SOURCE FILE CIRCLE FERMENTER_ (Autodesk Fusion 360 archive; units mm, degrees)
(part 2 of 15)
sketch "Schizzo17" plane through (0, 0, -13.5) normal (0, 0, 1) x axis (-1, 0, 0)
  line L1 (-125, 90) -> (-125, 88.4)
  line L2 (-160, 90) -> (-125, 90)
  line L3 (-160, 88.4) -> (-160, 90)
  curve K1 (-142.5, 81.4) -> (-160, 88.4)
  curve K2 (-135, 85.4) -> (-142.5, 81.4)
  line L4 (-135, 88.4) -> (-135, 85.4)
  line L5 (-125, 88.4) -> (-135, 88.4)
  line L6 (-136.6, 88.4) -> (-136.6, 86.8515)
  line L7 (-152.9954, 88.4) -> (-136.6, 88.4)
  curve K3 (-142.5, 83) -> (-152.9954, 88.4)
  curve K4 (-136.6, 86.8515) -> (-142.5, 83)
  line L8 (-138.6, 88.4) -> (-138.6, 86.0053)
  point P13 (-138.6, 86.0053)
  point P14 (-138.6, 88.4)
  coincident K4 P13
  coincident L7 P14
  perpendicular L7 L8
  dimension "d275" = -1.6
  dimension "d672" distance L6 L8 = 2
extrude "Estrusione20" cut sketch "Schizzo17" profile of K3 K4 L7 L8 against normal blind 50
sweep "Sweep3" TwistAngle 0 TaperAngle 0
fillet "Raccordo1" radius 0.5
extrude "Estrusione21" cut of existing geometry blind -45 (= "-120 mm + 75 mm")
sketch "Schizzo18" plane through (0, -15, 0) normal (0, 1, 0) x axis (-1, 0, 0)
  line L1 (-150.8209, -86.9) -> (-138.6, -86.9)
  curve K1 (-150.8209, -86.9) -> (-151.0572, -85.9594)
  curve K2 (-142.5, -81.5) -> (-151.0572, -85.9594)
  curve K3 (-138.6, -84.5053) -> (-142.5, -81.5)
  line L2 (-125, -86.9) -> (-125, -88.5)
  line L3 (-135, -86.9) -> (-125, -86.9)
  line L4 (-135, -83.9) -> (-135, -86.9)
  curve K4 (-135, -83.9) -> (-142.5, -79.9)
  curve K5 (-142.5, -79.9) -> (-160, -86.9)
  line L5 (-160, -88.5) -> (-160, -86.9)
  line L6 (-125, -88.5) -> (-160, -88.5)
  line L7 (-138.6, -86.9) -> (-138.6, -84.5053)
  circle C1 centre (-135.4, -85.4) radius 0.85
  point P14 (-135.4, -85.4)
  dimension "DIAM_SEDE_GUARNIZOIONE" diameter C1 = 1.7
  dimension "d669" distance L4 P14 = 0.4
  dimension "d671" distance L3 P14 = 1.5
sweep "Sweep4" sketch "Schizzo18" TwistAngle 0 TaperAngle 0
mirror "Specchio2" mirrorStitchTolerance 0.1
sketch "Schizzo19" plane through (0, -15, 0) normal (0, 1, 0) x axis (-1, 0, 0)
  line L1 (-135, -83.9) -> (-135, -84.65)
  curve K1 (-135, -83.9) -> (-142.5, -79.9)
  curve K2 (-142.5, -79.9) -> (-160, -86.9)
  line L2 (-160, -88.5) -> (-160, -86.9)
  line L3 (-125, -88.5) -> (-160, -88.5)
  line L4 (-125, -86.9) -> (-125, -88.5)
  line L5 (-135, -86.9) -> (-125, -86.9)
  line L6 (-150.8209, -86.9) -> (-138.6, -86.9)
  curve K3 (-150.8209, -86.9) -> (-151.0572, -85.9594)
  curve K4 (-142.5, -81.5) -> (-151.0572, -85.9594)
  curve K5 (-138.6, -84.5053) -> (-142.5, -81.5)
  line L7 (-135, -86.15) -> (-135, -86.9)
  line L8 (-138.6, -86.9) -> (-138.6, -84.5053)
  arc A1 centre (-135.4, -85.4) radius 0.85 clockwise from (-135, -86.15) to (-135, -84.65)
  arc A2 centre (-135.4, -85.4) radius 0.85 clockwise from (-135, -86.15) to (-135, -84.65)
  circle C1 centre (-135.4, -85.4) radius 0.875
  concentric A2 C1
  dimension "d305" diameter C1 = 1.75
sweep "Sweep5" sketch "Schizzo19" TwistAngle 0 TaperAngle 0 bodies "GUARNIZIONE"
mirror "Specchio3" mirrorStitchTolerance 0.1 bodies "GUARNIZIONE (1)"
work_plane "Piano di lavoro2" AlongDistance -2
sketch "Schizzo21" plane through (158, 0, 0) normal (1, 0, 0) x axis (0, 1, 0)
  line L1 (-81.4, -63.5) -> (-81.4, -13.5)
  curve K1 (-81.4, -63.5) -> (-65, -79.9)
  line L2 (-65, -79.9) -> (-15, -79.9)
  line L3 (-65, -81.4) -> (-15, -81.4)
  curve K2 (-82.9, -63.5) -> (-65, -81.4)
  line L4 (-82.9, -63.5) -> (-82.9, -13.5)
  line L5 (-15, -13.5) -> (-15, -81.4)
  line L6 (-82.9, -13.5) -> (-15, -13.5)
  horizontal L6
  vertical L5
  dimension "d329" = -1.5
extrude "Estrusione23" new body sketch "Schizzo21" profile of L3 K2 L4 L5 L6 against normal blind 3 bodies "TEST ACRILICO DAVANTI"
sketch "Schizzo22" plane through (0, 0, -13.5) normal (0, 0, 1) x axis (-1, 0, 0)
  line L1 (-125, 88.4) -> (-135, 88.4)
  line L2 (-125, 90) -> (-125, 88.4)
  line L3 (-160, 90) -> (-125, 90)
  line L4 (-160, 88.4) -> (-160, 90)
  curve K1 (-142.5, 81.4) -> (-160, 88.4)
  curve K2 (-135, 85.4) -> (-142.5, 81.4)
  line L5 (-135, 88.4) -> (-135, 87.65)
  curve K3 (-142.5, 83) -> (-138.6, 86.0053)
  curve K4 (-151.0572, 87.4594) -> (-142.5, 83)
  curve K5 (-151.0572, 87.4594) -> (-150.8209, 88.4)
  line L6 (-138.6, 88.4) -> (-150.8209, 88.4)
  curve K6 (-142.5, 80.9) -> (-160, 87.9)
  line L7 (-160, 90) -> (-160, 87.9)
  line L8 (-158, 15) -> (-158, 82.9)
  line L9 (-155, 15) -> (-158, 15)
  line L10 (-155, 82.9) -> (-155, 15)
  line L11 (-158, 82.9) -> (-155, 82.9)
  line L12 (-158, 82.9) -> (-158, 77.9)
  line L13 (-155, 82.9) -> (-158, 82.9)
  line L14 (-155, 86.9365) -> (-155, 82.9)
  curve K7 (-164, 77.9) -> (-158, 77.9)
  curve K8 (-168, 77.9) -> (-164, 77.9)
  curve K9 (-170, 88.4) -> (-168, 77.9)
  curve K10 (-174, 88.4) -> (-170, 88.4)
  curve K11 (-180, 88.4) -> (-174, 88.4)
  curve K12 (-180, 88.4) -> (-158, 77.9)
  line L15 (-160, 90) -> (-160, 87.9)
  line L16 (-180, 90) -> (-160, 90)
  line L17 (-180, 88.4) -> (-180, 90)
  line L18 (-151.4, 82.9) -> (-155, 82.9)
  line L19 (-151.4, 85.247) -> (-151.4, 82.9)
  line L20 (-138.6, 86.0053) -> (-138.6, 88.4)
  line L21 (-135, 86.15) -> (-135, 85.4)
  arc A1 centre (-135.4, 86.9) radius 0.85 clockwise from (-135, 86.15) to (-135, 87.65)
  point P7 (-160, 90)
  point P18 (-160, 90)
  point P23 (-158, 77.9)
  point P19 (-158, 82.9)
  point P24 (-158, 82.9)
  point P22 (-155, 82.9)
  point P25 (-155, 82.9)
  point P26 (-155, 82.9)
  point P27 (-155, 86.9365)
  point P33 (-160, 90)
  point P36 (-151.4, 85.247)
  point P28 (-164, 77.9)
  point P29 (-168, 77.9)
  point P31 (-174, 88.4)
  point P32 (-180, 88.4)
  point P30 (-170, 88.4)
  point P34 (-180, 90)
  point P35 (-151.4, 82.9)
  coincident P7 P18
  perpendicular L3 L7
  coincident L8 P23
  coincident P19 P24
  perpendicular L11 L12
  coincident P22 P25
  coincident P22 P26
  coincident K6 P27
  perpendicular L11 L14
  horizontal K10
  horizontal K7
  perpendicular L15 L16
  parallel L15 L17
  horizontal K8
  horizontal K11
  coincident P18 P33
  perpendicular L14 L18
  coincident K6 P36
  perpendicular L18 L19
  dimension "d332" = 0.5
  dimension "d335" distance P23 P24 = 5
  dimension "d336" distance L3 L13 = 7.1
  dimension "d337" distance P23 P28 = 6
  dimension "d338" distance P23 P29 = 10
  dimension "d339" distance P31 P32 = 6
  dimension "d340" distance P30 P32 = 10
  dimension "d342" distance P32 P34 = 1.6
  dimension "d343" distance P33 P34 = 20
  dimension "d373" distance P25 P35 = 3.6
extrude "Estrusione24" new body sketch "Schizzo22" profile of L4 K6 L7 L8 L11 L12 L13 L14 K12 L15 L16 L17 against normal blind 50
sweep "Sweep6" TwistAngle 0 TaperAngle 0 bodies "PROFILO BASE PORTA"
remove_body "RimuoviCorpo1"
chamfer "Smusso2" distance 0.8
component_from_bodies "Corpo->Comp1"
component_from_bodies "Corpo->Comp2"
copy_paste "CopiaIncolla1"
extrude "Estrusione1" add of existing geometry blind 27.5 (= "( 205 / 2 ) * 1 mm - 75 mm")
extrude "Estrusione2" add of existing geometry blind 15 (= "90 mm - 75 mm")
remove_instance "RimuoviIstanza1"
extrude "Estrusione3" add of existing geometry blind 85 (= "( 320 / 2 ) * 1 mm - 75 mm")
mirror_component "SpecchiaComponente1"
derived_instance "DerivedInstance1"
mirror_component "SpecchiaComponente2"
derived_instance "DerivedInstance2"
derived_instance "DerivedInstance3"
copy_paste "CopiaIncolla2"
extrude "Estrusione1" add of existing geometry blind 15
extrude "Estrusione2" add of existing geometry blind 27.5
sketch "Schizzo3" plane through (0, 0, 0) normal (0, 1, 0) x axis (-1, 0, 0)
  line L1 (-160, -87.7) -> (-160.8, -88.5)
  line L2 (-160, -86.4) -> (-160, -87.7)
  curve K1 (-151.4, -83.747) -> (-160, -86.4)
  line L3 (-151.4, -81.4) -> (-151.4, -83.747)
  line L4 (-158, -81.4) -> (-151.4, -81.4)
  line L5 (-158, -76.4) -> (-158, -81.4)
  curve K2 (-180, -86.9) -> (-158, -76.4)
  line L6 (-180, -88.5) -> (-180, -86.9)
  line L7 (-160.8, -88.5) -> (-180, -88.5)
  line L8 (-158, -86.2311) -> (-158, -81.4)
  point P7 (-158, -81.4)
  point P11 (-158, -81.4)
  point P12 (-158, -86.2311)
  coincident P7 P11
  coincident K1 P12
  perpendicular L4 L8
extrude "Estrusione5" cut sketch "Schizzo3" profile of K1 L3 L4 L8 against normal blind 65
sketch "Schizzo4" plane through (0, 0, 14) normal (0, 0, 1) x axis (-1, 0, 0)
  line L1 (-160.8, 90) -> (-160, 89.2)
  line L2 (-180, 90) -> (-160.8, 90)
  line L3 (-180, 88.4) -> (-180, 90)
  curve K1 (-158, 77.9) -> (-180, 88.4)
  line L4 (-158, 82.9) -> (-158, 77.9)
  line L5 (-151.4, 82.9) -> (-158, 82.9)
  line L6 (-151.4, 85.247) -> (-151.4, 82.9)
  curve K2 (-160, 87.9) -> (-151.4, 85.247)
  line L7 (-160, 89.2) -> (-160, 87.9)
  line L8 (-158, 87.7311) -> (-158, 82.9)
  point P7 (-158, 82.9)
  point P11 (-158, 82.9)
  point P12 (-158, 87.7311)
  coincident P7 P11
  coincident K2 P12
  perpendicular L5 L8
extrude "Estrusione6" cut sketch "Schizzo4" profile of L5 L6 K2 L8 against normal blind 77.5 alignOffsetY 0
sketch "Schizzo6" plane through (158, 0, 0) normal (-1, 0, 0) x axis (0, -1, 0)
  curve K1 (65, -76.4) -> (77.9, -63.5)
  line L1 (0, -76.4) -> (65, -76.4)
  line L2 (0, -86.2311) -> (0, -76.4)
  line L3 (0, -86.2311) -> (65, -86.2311)
  line L4 (65, -81.4) -> (65, -86.2311)
  curve K2 (65, -81.4) -> (82.9, -63.5)
  line L5 (87.7311, -63.5) -> (82.9, -63.5)
  line L6 (87.7311, -63.5) -> (87.7311, 14)
  line L7 (77.9, 14) -> (87.7311, 14)
  line L8 (77.9, -63.5) -> (77.9, 14)
  line L9 (86.9, -62.4362) -> (86.9, -63.5)
  line L10 (86.9, 14) -> (86.9, -62.4362)
  line L11 (0, -85.4) -> (65, -85.4)
  line L12 (0, 14) -> (0, -85.4)
  line L13 (86.9, 14) -> (0, 14)
  point P12 (86.9, -63.5)
  point P14 (86.9, 14)
  point P15 (65, -85.4)
  point P16 (0, -85.4)
  coincident L5 P12
  perpendicular L5 L9
  coincident L7 P14
  perpendicular L7 L10
  coincident L4 P15
  coincident L2 P16
  perpendicular L2 L11
  horizontal L13
  vertical L12
  dimension "d398" distance L10 L12 = 86.9
  dimension "d399" distance L11 L13 = 99.4
extrude "Estrusione7" new body sketch "Schizzo6" profile of K1 L1 L2 L4 K2 L5 L7 L8 L9 L10 L11 L12 L13 along normal blind 3 bodies "ACRILICO SPORTELLO"
sketch "Schizzo7" plane through (0, 0, 14) normal (0, 0, 1) x axis (-1, 0, 0)
  line L1 (-158, 87.7311) -> (-158, 77.9)
  curve K1 (-160, 87.9) -> (-158, 87.7311)
  line L2 (-160, 89.2) -> (-160, 87.9)
  line L3 (-160.8, 90) -> (-160, 89.2)
  line L4 (-180, 90) -> (-160.8, 90)
  line L5 (-180, 88.4) -> (-180, 90)
  curve K2 (-158, 77.9) -> (-180, 88.4)
  line L6 (-151.4, 85.247) -> (-151.4, 82.9)
  curve K3 (-151.4, 85.247) -> (-158, 87.7311)
  line L7 (-158, 82.9) -> (-158, 87.7311)
  line L8 (-151.4, 82.9) -> (-158, 82.9)
  line L9 (-158, 0) -> (-158, 86.9)
  line L10 (-155, 0) -> (-158, 0)
  line L11 (-155, 86.9) -> (-155, 0)
  line L12 (-158, 86.9) -> (-155, 86.9)
  line L13 (-155, 88.0285) -> (-155, 86.9)
  point P16 (-155, 86.9)
  point P17 (-155, 86.9)
  coincident P16 P17
  perpendicular L12 L13
extrude "Estrusione8" new body sketch "Schizzo7" profile of L6 K3 L8 L11 L13 against normal blind 77.5
sketch "Schizzo8" plane through (0, 0, 0) normal (0, 1, 0) x axis (-1, 0, 0)
  line L1 (-158, -76.4) -> (-158, -86.2311)
  curve K1 (-180, -86.9) -> (-158, -76.4)
  line L2 (-180, -88.5) -> (-180, -86.9)
  line L3 (-160.8, -88.5) -> (-180, -88.5)
  line L4 (-160, -87.7) -> (-160.8, -88.5)
  line L5 (-160, -86.4) -> (-160, -87.7)
  curve K2 (-158, -86.2311) -> (-160, -86.4)
  line L6 (-158, -85.4) -> (-158, 14)
  line L7 (-155, -85.4) -> (-158, -85.4)
  line L8 (-155, 14) -> (-155, -85.4)
  line L9 (-158, 14) -> (-155, 14)
  line L10 (-158, -86.2311) -> (-158, -81.4)
  curve K3 (-151.4, -83.747) -> (-158, -86.2311)
  line L11 (-151.4, -81.4) -> (-151.4, -83.747)
  line L12 (-158, -81.4) -> (-151.4, -81.4)
  line L13 (-155, -87.0144) -> (-155, -85.4)
  point P11 (-155, -85.4)
  point P17 (-155, -85.4)
  coincident P11 P17
  perpendicular L7 L13
extrude "Estrusione9" new body sketch "Schizzo8" profile of L8 K3 L11 L12 L13 against normal blind 65
sketch "Schizzo9" plane through (155, 0, 0) normal (-1, 0, 0) x axis (0, -1, 0)
  line L1 (65, -81.4) -> (65, -85.4)
  curve K1 (82.9, -63.5) -> (65, -81.4)
  line L2 (86.9, -63.5) -> (82.9, -63.5)
  line L3 (86.9, 14) -> (86.9, -63.5)
  line L4 (0, 14) -> (86.9, 14)
  line L5 (0, -85.4) -> (0, 14)
  line L6 (65, -85.4) -> (0, -85.4)
  curve K2 (65, -76.4) -> (77.9, -63.5)
  line L7 (77.9, 14) -> (77.9, -63.5)
  line L8 (0, -76.4) -> (65, -76.4)
  line L9 (65, -81.4) -> (0, -81.4)
  line L10 (82.9, 14) -> (85.247, 14)
  line L11 (82.9, -63.5) -> (82.9, 14)
  line L12 (85.247, -63.5) -> (82.9, -63.5)
  line L13 (85.247, 14) -> (85.247, -63.5)
extrude "Estrusione10" add sketch "Schizzo9" profile of K1 L4 L5 K2 L7 L8 L9 L11 along normal blind 3.6
sketch "Schizzo10" plane through (151.4, 0, 0) normal (-1, 0, 0) x axis (0, -1, 0)
  line L1 (77.9, 14) -> (85.247, 14)
  line L2 (77.9, -63.5) -> (77.9, 14)
  curve K1 (65, -76.4) -> (77.9, -63.5)
  line L3 (0, -76.4) -> (65, -76.4)
  line L4 (0, -83.747) -> (0, -76.4)
  line L5 (65, -83.747) -> (0, -83.747)
  line L6 (65, -81.4) -> (65, -83.747)
  curve K2 (82.9, -63.5) -> (65, -81.4)
  line L7 (85.247, -63.5) -> (82.9, -63.5)
  line L8 (85.247, 14) -> (85.247, -63.5)
  line L9 (65, -63.5) -> (65, -81.4)
  line L10 (82.9, -63.5) -> (65, -63.5)
  line L11 (91.705, -90.205) -> (65, -63.5)
  line L12 (65, -80.0735) -> (0, -80.0735)
  line L13 (81.5735, -63.5) -> (81.5735, 14)
  point P9 (65, -81.4)
  point P12 (65, -81.4)
  point P10 (82.9, -63.5)
  point P14 (82.9, -63.5)
  point P16 (0, -80.0735)
  point P17 (65, -80.0735)
  point P18 (0, -80.0735)
  point P19 (45, -80.0735)
  point P20 (81.5735, 14)
  point P21 (81.5735, -63.5)
  point P22 (81.5735, -43.5)
  point P23 (81.5735, 14)
  coincident P9 P12
  parallel L6 L9
  coincident P10 P14
  horizontal L10
  midpoint L4 P16
  coincident L9 P17
  perpendicular L9 L12
  coincident L12 P18
  coincident L12 P19
  midpoint L1 P20
  coincident L10 P21
  perpendicular L10 L13
  coincident L13 P22
  coincident L13 P23
  coincident P16 P18
  coincident P20 P23
  dimension "d406" angle L10 L11 = 45
  dimension "d408" distance P18 P19 = 45
  dimension "d409" distance L6 P19 = 20
  dimension "d410" distance P21 P22 = 20
  dimension "d413" distance P20 P22 = 57.5
  dimension "d648" distance P22 P23 = 57.5
hole "Foratura1" HoleDepth 12 HoleDiameter 3.5 TipAngle 180 CBDepth 3 CBDiameter 6
fillet "Raccordo2" radius 0.5
mirror "Specchio3" mirrorStitchTolerance 0.1
mirror "Specchio4" mirrorStitchTolerance 0.1
step "Vite5"
joint "Assembla5" alignAngle 0 alignOffsetX 0 alignOffsetY 0 alignOffsetZ 0
step "Vite6"
joint "Assembla6" alignAngle 0 alignOffsetX 0 alignOffsetY 0 alignOffsetZ 0
step "Vite7"
joint "Assembla7" alignAngle 0 alignOffsetX 0 alignOffsetY 0 alignOffsetZ 0
step "Vite8"
joint "Assembla8" alignAngle 0 alignOffsetX 0 alignOffsetY 0 alignOffsetZ 0
step "Vite9"
joint "Assembla9" alignAngle 0 alignOffsetX 0 alignOffsetY 0 alignOffsetZ 0
step "Vite10"
joint "Assembla10" alignAngle 0 alignOffsetX 0 alignOffsetY 0 alignOffsetZ 0
step "Vite11"
joint "Assembla11" alignAngle 0 alignOffsetX 0 alignOffsetY 0 alignOffsetZ 0
step "Vite12"
joint "Assembla12" alignAngle 0 alignOffsetX 0 alignOffsetY 0 alignOffsetZ 0
step "Vite13"
joint "Assembla13" alignAngle 0 alignOffsetX 0 alignOffsetY 0 alignOffsetZ 0
step "Vite14"
joint "Assembla14" alignAngle 0 alignOffsetX 0 alignOffsetY 0 alignOffsetZ 0
step "Vite15"
joint "Assembla15" alignAngle 0 alignOffsetX 0 alignOffsetY 0 alignOffsetZ 0
step "Vite16"
joint "Assembla16" alignAngle 0 alignOffsetX 0 alignOffsetY 0 alignOffsetZ 0
step "Vite17"
joint "Assembla17" alignAngle 0 alignOffsetX 0 alignOffsetZ 0
step "Vite18"
joint "Assembla18" alignAngle 0 alignOffsetX 0 alignOffsetY 0 alignOffsetZ 0
step "Vite19"
joint "Assembla19" alignAngle 0 alignOffsetX 0 alignOffsetY 0 alignOffsetZ 0
step "Vite20"
joint "Assembla20" alignAngle 0 alignOffsetX 0 alignOffsetY 0 alignOffsetZ 0
component_from_bodies "Corpo->Comp1"
mirror "Specchio5" mirrorStitchTolerance 0.1
mirror "Specchio6" mirrorStitchTolerance 0.1
component_from_bodies "Corpo->Comp2"
thread "Filettatura1"
mirror "Specchio1" mirrorStitchTolerance 0.1
mirror "Specchio2" mirrorStitchTolerance 0.1
component_from_bodies "Corpo->Comp3"
joint "Assembla21" alignAngle 0 alignOffsetX 0 alignOffsetY 0 alignOffsetZ 0
joint "Assembla22" alignAngle 0 alignOffsetX 0 alignOffsetY 0 alignOffsetZ 0
chamfer "Smusso1" distance 1
sketch "Schizzo1" plane through (0, 0, 0) normal (-1, 0, 0) x axis (0, -1, 0)
  curve K1 (66.6, -86.8951) -> (88.3975, -65.1)
  line L1 (66.6, -85.4521) -> (66.6, -86.8951)
  curve K2 (79.5815, -78.0815) -> (66.6, -85.4521)
  curve K3 (86.9521, -65.1) -> (79.5815, -78.0815)
  line L2 (88.3975, -65.1) -> (86.9521, -65.1)
  line L3 (85.4, -63.5) -> (86.15, -63.5)
  curve K4 (78.4501, -76.9501) -> (85.4, -63.5)
  curve K5 (65, -83.9) -> (78.4501, -76.9501)
  line L4 (65, -84.65) -> (65, -83.9)
  line L5 (55, -86.9) -> (65, -86.9)
  line L6 (55, -88.5) -> (55, -86.9)
  line L7 (65, -88.5) -> (55, -88.5)
  curve K6 (90, -63.5) -> (65, -88.5)
  line L8 (90, -53.5) -> (90, -63.5)
  line L9 (88.4, -53.5) -> (90, -53.5)
  line L10 (88.4, -63.5) -> (88.4, -53.5)
  line L11 (65, -86.9) -> (65, -86.15)
  line L12 (87.65, -63.5) -> (88.4, -63.5)
  arc A1 centre (86.9, -63.9) radius 0.85 clockwise from (87.65, -63.5) to (86.15, -63.5)
  arc A2 centre (65.4, -85.4) radius 0.85 clockwise from (65, -84.65) to (65, -86.15)
extrude "Estrusione1" new body sketch "Schizzo1" profile of K1 L1 K2 K3 L2 against normal blind 30
fillet "Raccordo1" radius 1
work_plane "Piano di lavoro1"
remove_instance "RimuoviIstanza1"
remove_body "RimuoviCorpo4"
component_from_bodies "Corpo->Comp3"
component_from_bodies "Corpo->Comp4"
extrude "Estrusione1" add of existing geometry blind 85
extrude "Estrusione2" add of existing geometry blind 27.5
extrude "Estrusione1" add of existing geometry blind 85
extrude "Estrusione2" add of existing geometry blind 15
remove_body "RimuoviCorpo7"
remove_body "RimuoviCorpo8"
sketch "Schizzo2" plane through (0, -79.2125, -79.2737) normal (0, -0.7068, -0.7074) x axis (1, 0, 0)
  line L1 (0, 11.5655) -> (30, 11.5655)
  line L2 (30, 11.5655) -> (30, 1.1037)
  line L3 (0, 1.1037) -> (30, 1.1037)
  line L4 (0, 11.5655) -> (0, 1.1037)
  line L5 (30, -9.3661) -> (0, -9.3661)
  line L6 (0, 1.1037) -> (0, -9.3661)
  line L7 (30, 1.1037) -> (0, 1.1037)
  line L8 (30, 1.1037) -> (30, -9.3661)
  circle C1 centre (15, 1.1037) radius 2
  point P10 (15, 1.1037)
  coincident L7 P10
  dimension "d529" diameter C1 = 4
  dimension "d544" distance L8 P10 = 15
extrude "Estrusione2" cut sketch "Schizzo2" profile of L3 L7 C1 distance -14.039
work_axis "AsseLavoro1"
work_plane "Piano di lavoro2" RotateAngle 0
sketch "Schizzo3" plane through (15, 0, 0) normal (1, 0, 0) x axis (0, 1, 0)
  curve K1 (-71.4268, -84.7327) -> (-71.7899, -86.6906)
  curve K2 (-71.7899, -86.6906) -> (-88.1875, -70.3056)
  curve K3 (-88.1875, -70.3056) -> (-86.2311, -69.9353)
  curve K4 (-86.2311, -69.9353) -> (-79.5815, -78.0815)
  curve K5 (-79.5815, -78.0815) -> (-71.4268, -84.7327)
  curve K6 (-71.7899, -86.6906) -> (-71.4268, -84.7327)
  curve K7 (-79.5815, -78.0815) -> (-71.4268, -84.7327)
  curve K8 (-86.2311, -69.9353) -> (-79.5815, -78.0815)
  curve K9 (-86.2311, -69.9353) -> (-88.1875, -70.3056)
  curve K10 (-71.7899, -86.6906) -> (-88.1875, -70.3056)
  line L1 (-85.3935, -83.898) -> (-72.103, -70.5972)
  line L2 (-82.9743, -81.4769) -> (-83.3984, -81.9013)
  line L3 (-77.3152, -87.1316) -> (-82.9743, -81.4769)
  line L4 (-77.7393, -87.556) -> (-83.3984, -81.9013)
  line L5 (-77.3152, -87.1316) -> (-77.7393, -87.556)
  line L6 (-88.6333, -75.8222) -> (-82.9743, -81.4769)
  line L7 (-82.9743, -81.4769) -> (-83.3984, -81.9013)
  line L8 (-88.6333, -75.8222) -> (-89.0574, -76.2466)
  line L9 (-89.0574, -76.2466) -> (-83.3984, -81.9013)
  line L10 (-94.0535, -81.2466) -> (-89.0574, -76.2466)
  line L11 (-82.7355, -92.556) -> (-94.0535, -81.2466)
  line L12 (-77.7393, -87.556) -> (-82.7355, -92.556)
  point P14 (-83.3984, -81.9013)
  point P20 (-83.3984, -81.9013)
  point P15 (-82.9743, -81.4769)
  point P18 (-82.9743, -81.4769)
  point P16 (-77.3152, -87.1316)
  point P19 (-88.6333, -75.8222)
  point P17 (-77.7393, -87.556)
  point P21 (-89.0574, -76.2466)
  point P23 (-82.7355, -92.556)
  coincident K10 P14
  coincident L1 P14
  parallel L1 L2
  perpendicular L1 L3
  perpendicular L1 L4
  perpendicular L4 L5
  symmetric L1 P14 P20
  symmetric L1 P15 P18
  symmetric L1 P16 P19
  symmetric L1 P17 P21
  perpendicular L9 L10
  perpendicular L10 L11
  perpendicular L11 L12
  dimension "d534" distance P14 P15 = 0.6
  dimension "d535" distance P14 P17 = 8
  dimension "d539" distance P17 P23 = 5
extrude "Estrusione3" cut sketch "Schizzo3" profile of K2 K10 L1 L2 L3 L4 L5 L6 L7 L8 L9 L10 L11 L12 distance 18.695
work_plane "Piano di lavoro3" RotateAngle 135
sketch "Schizzo4" plane through (0, -78.8315, -78.8315) normal (0, -0.7071, -0.7071) x axis (1, 0, 0)
  curve K1 (13, 1.0607) -> (17, 1.0607)
  curve K2 (17, 1.0607) -> (13, 1.0607)
  line L1 (15, 1.0575) -> (15, 1.0647)
  circle C1 centre (15, 1.0647) radius 5
  point P4 (15, 1.0647)
  point P6 (15, 1.0647)
  coincident P4 P6
  dimension "d541" diameter C1 = 10
extrude "Estrusione4" cut sketch "Schizzo4" profile of K1 K2 C1 along normal blind 0.8
fillet "Raccordo2" radius 1 1
mirror "Specchio1" mirrorStitchTolerance 0.1
component_from_bodies "Corpo->Comp1"
component_insert "Inserimento componente1"
component_insert "Inserimento componente2"
joint "Assembla1" alignAngle 0 alignOffsetX 0 alignOffsetY 0 alignOffsetZ 0
joint "Assembla2" alignAngle 0 alignOffsetX 0 alignOffsetY 0 alignOffsetZ 0
work_plane "Piano di lavoro1" RotateAngle 45
sketch "Schizzo1" plane through (0, -77.7001, -77.7001) normal (0, 0.7071, 0.7071) x axis (-1, 0, 0)
  line L1 (0, 1.0607) -> (0, 15.4856)
  line L2 (0, 1.0607) -> (-85, 1.0607)
  line L3 (-16, 1.0607) -> (0, 1.0607)
  point P3 (0, 1.0607)
  point P5 (0, 1.0607)
  point P6 (-16, 1.0607)
  point P7 (-16, 1.0607)
  point P8 (-14, 1.0607)
  coincident P3 P5
  perpendicular L1 L3
  coincident P6 P7
  coincident L2 P8
  dimension "d560" distance P5 P6 = 16
  dimension "d561" distance P7 P8 = 2
hole "Foratura1" HoleDepth 6 HoleDiameter 3.5 TipAngle 180 CSDiameter 6.7 CSAngle 90
sketch "Schizzo2" plane through (0, -77.7001, -77.7001) normal (0, 0.7071, 0.7071) x axis (-1, 0, 0)
  curve K1 (-10.65, 1.0607) -> (-15, 4.0417)
  line L1 (-15, 4.0417) -> (-15, 2.4968)
  curve K2 (-15, -1.9204) -> (-10.65, 1.0607)
  curve K3 (-15, 4.0417) -> (-19.35, 1.0607)
  curve K4 (-19.35, 1.0607) -> (-15, -1.9204)
  line L2 (-15, -0.3755) -> (-15, -1.9204)
  line L3 (-16.8101, -0.4905) -> (-13.1899, 2.6119)
  line L4 (-17, -0.6893) -> (-13, -0.6893)
  line L5 (-15, -0.3755) -> (-15, -1.9204)
  line L6 (-15, 4.0417) -> (-15, 2.4968)
  arc A1 centre (-14, 1.0607) radius 1.75 clockwise from (-15, 2.4968) to (-12.25, 1.0607)
  arc A2 centre (-16, 1.0607) radius 1.75 clockwise from (-15, -0.3755) to (-17.75, 1.0607)
  arc A3 centre (-14, 1.0607) radius 1.75 clockwise from (-12.25, 1.0607) to (-15, -0.3755)
  arc A4 centre (-16, 1.0607) radius 1.75 clockwise from (-17.75, 1.0607) to (-15, 2.4968)
  point P14 (-13.1899, 2.6119)
  point P15 (-16.8101, -0.4905)
  midpoint A1 P14
  midpoint A2 P15
work_plane "Piano di lavoro2" AlongDistance -15
sketch "Schizzo4" plane through (15, 0, 0) normal (-1, 0, 0) x axis (0, -1, 0)
  line L1 (79.5815, -78.0815) -> (78.344, -79.3189)
  curve K1 (80.7035, -74.9877) -> (78.4501, -76.9501)
  curve K2 (78.4501, -76.9501) -> (76.4877, -79.2035)
  line L2 (80.8189, -74.8943) -> (80.8189, -76.844)
  line L3 (76.3943, -79.3189) -> (78.344, -79.3189)
  curve K3 (78.566, -79.097) -> (76.4877, -79.2035)
  line L4 (80.8189, -76.844) -> (79.5815, -78.0815)
  curve K4 (80.7035, -74.9877) -> (80.597, -77.066)
  point P8 (80.8189, -74.8943)
  point P2 (78.344, -79.3189)
  point P9 (78.344, -79.3189)
  point P10 (76.3943, -79.3189)
  coincident K1 P8
  vertical L2
  coincident P2 P9
  coincident K2 P10
  perpendicular L2 L3
extrude "Estrusione5" cut sketch "Schizzo4" distance 1
copy_paste "CopiaIncolla1"
remove_instance "RimuoviIstanza1"
extrude "Estrusione39" add sketch "Schizzo30" profile of L5 K1 L6 L7 K2 L8 L9 L10 against normal blind 120
extrude "Estrusione40" cut of existing geometry blind -39.926
extrude "Estrusione41" cut of existing geometry blind -32.169
sketch "Schizzo1" plane through (-30, 0, 0) normal (-1, 0, 0) x axis (0, -1, 0)
  line L1 (85.8919, -78.5615) -> (80.0566, -84.3923)
  curve K1 (85.8919, -78.5615) -> (88.1875, -70.3056)
  curve K2 (86.2311, -69.9353) -> (88.1875, -70.3056)
  curve K3 (86.2311, -69.9353) -> (79.5815, -78.0815)
  curve K4 (79.5815, -78.0815) -> (71.4268, -84.7327)
  curve K5 (71.7899, -86.6906) -> (71.4268, -84.7327)
  curve K6 (71.7899, -86.6906) -> (80.0566, -84.3923)
  line L2 (85.7303, -78.4402) -> (79.9356, -84.2305)
  curve K7 (85.7303, -78.4402) -> (87.9884, -70.2871)
  curve K8 (86.4232, -69.9908) -> (87.9884, -70.2871)
  curve K9 (86.4232, -69.9908) -> (79.7229, -78.2229)
  curve K10 (79.7229, -78.2229) -> (71.4814, -84.9251)
  curve K11 (71.7719, -86.4914) -> (71.4814, -84.9251)
  curve K12 (71.7719, -86.4914) -> (79.9356, -84.2305)
  line L3 (88.088, -69.2165) -> (87.9884, -70.2871)
  line L4 (70.2461, -86.629) -> (71.7719, -86.4914)
  dimension "d572" = 0.2
extrude "Estrusione1" cut sketch "Schizzo1" profile of L1 K1 K2 K5 K6 L2 K7 K12 L3 L4 against normal blind 60
sketch "Schizzo1" plane through (0, 0, 0) normal (0, 1, 0) x axis (-1, 0, 0)
  line L1 (-135, -83.9) -> (-135, -84.65)
  curve K1 (-142.5, -79.9) -> (-135, -83.9)
  curve K2 (-160, -86.9) -> (-142.5, -79.9)
  line L2 (-160, -88.5) -> (-160, -86.9)
  line L3 (-125, -88.5) -> (-160, -88.5)
  line L4 (-125, -86.9) -> (-125, -88.5)
  line L5 (-135, -86.9) -> (-125, -86.9)
  line L6 (-150.8209, -86.9) -> (-139.6, -86.9)
  curve K3 (-151.0572, -85.9594) -> (-150.8209, -86.9)
  curve K4 (-142.5, -81.5) -> (-151.0572, -85.9594)
  curve K5 (-139.3951, -83.8988) -> (-142.5, -81.5)
  line L7 (-135, -86.15) -> (-135, -86.9)
  line L8 (-138.6, -85.9) -> (-138.6, -85.5053)
  line L9 (-139.6, -86.9) -> (-138.6, -85.9)
  line L10 (-139.3951, -83.8988) -> (-138.6, -85.5053)
  arc A1 centre (-135.4, -85.4) radius 0.85 clockwise from (-135, -86.15) to (-135, -84.65)
extrude "Estrusione1" new body sketch "Schizzo1" profile of L6 K3 K4 K5 against normal blind 15
work_plane "Piano di lavoro1" RotateAngle 45
sketch "Schizzo3" plane through (111.1565, 0, -111.1565) normal (-0.7071, 0, 0.7071) x axis (0, -1, 0)
  line L1 (0, 39.2418) -> (0, 43.1335)
  line L2 (15, 39.2418) -> (15, 43.1335)
  line L3 (0, 43.1335) -> (15, 43.1335)
  line L4 (0, 41.1335) -> (15, 41.1335)
  line L5 (15, 39.2418) -> (0, 39.2418)
  circle C1 centre (7.5, 41.1335) radius 2
  point P7 (15, 41.1335)
  point P8 (0, 41.1335)
  point P6 (7.5, 41.1335)
  coincident L2 P7
  coincident L1 P8
  perpendicular L1 L4
  coincident P6 L4
  dimension "d579" diameter C1 = 4
  dimension "d582" distance L3 L4 = 2
  dimension "d583" distance L1 P6 = 7.5
work_plane "Piano di lavoro2"
sketch "Schizzo6" plane through (0, 0, -86.9) normal (0, 0, -1) x axis (1, 0, 0)
  line L1 (150.8209, 0) -> (139.6, 0)
  line L2 (150.8209, 15) -> (150.8209, 0)
  line L3 (139.6, 15) -> (150.8209, 15)
  line L4 (143.3209, 15) -> (143.3209, 7.5)
  line L5 (139.6, 0) -> (139.6, 15)
  circle C1 centre (143.3209, 7.5) radius 2
  point P6 (143.3209, 7.5)
  point P7 (143.3209, 7.5)
  coincident P6 P7
  perpendicular L3 L4
  dimension "d588" diameter C1 = 4
  dimension "d597" distance L2 L4 = 7.5
extrude "Estrusione4" cut sketch "Schizzo6" profile of C1 against normal blind 16.833
work_axis "AsseLavoro2"
work_plane "Piano di lavoro3" AlongDistance -4
sketch "Schizzo7" plane through (0, 0, -82.9) normal (0, 0, -1) x axis (-1, 0, 0)
  circle C1 centre (-143.3209, -7.5) radius 4
  point P2 (-143.3209, -7.5)
  point P3 (-143.3209, -7.5)
  coincident P2 P3
  dimension "d592" diameter C1 = 8
extrude "Estrusione5" cut sketch "Schizzo7" against normal blind 3.353
fillet "Raccordo1" radius 0.4
component_insert "Inserimento componente1"
mirror "Specchio1" mirrorStitchTolerance 0.1
component_from_bodies "Corpo->Comp1"
joint "Assembla1" alignAngle 0 alignOffsetX 0 alignOffsetY 0 alignOffsetZ 0
component_insert "Inserimento componente2"
joint "Assembla2" alignAngle 0 alignOffsetX 0 alignOffsetY 0 alignOffsetZ 0
sketch "Schizzo6" plane through (0, 0, -88.5) normal (0, 0, -1) x axis (1, 0, 0)
  line L1 (95, 55) -> (0, 55)
  curve K1 (95, 55) -> (125, 25)
  line L2 (125, 0) -> (125, 25)
  line L3 (160, 0) -> (125, 0)
  line L4 (160, 65) -> (160, 0)
  line L5 (85, 65) -> (160, 65)
  line L6 (0, 65) -> (85, 65)
  line L7 (0, 55) -> (0, 65)
  curve K2 (95, 55) -> (125, 25)
  line L8 (125, 0) -> (125, 25)
  line L9 (95, 55) -> (0, 55)
  line L10 (95, 60) -> (0, 60)
  curve K3 (95, 60) -> (130, 25)
  line L11 (130, 0) -> (130, 25)
  point P18 (32, 60)
  point P14 (0, 60)
  point P15 (95, 60)
  point P16 (130, 25)
  point P17 (130, 0)
  coincident L10 P18
  dimension "d608" = 5
  dimension "d609" distance P14 P15 = 95
  dimension "d610" distance P16 P17 = 25
  dimension "d611" distance P14 P18 = 32
  dimension "d612" distance P15 P18 = 63
extrude "Estrusione6" cut of existing geometry blind -1
sketch "Schizzo7" plane through (0, 0, 0) normal (-1, 0, 0) x axis (0, -1, 0)
  curve K1 (66.6, -86.8951) -> (88.3975, -65.1)
  line L1 (66.6, -85.4521) -> (66.6, -86.8951)
  curve K2 (79.5815, -78.0815) -> (66.6, -85.4521)
  curve K3 (86.9521, -65.1) -> (79.5815, -78.0815)
  line L2 (88.3975, -65.1) -> (86.9521, -65.1)
  line L3 (85.4, -63.5) -> (86.15, -63.5)
  curve K4 (78.4501, -76.9501) -> (85.4, -63.5)
  curve K5 (65, -83.9) -> (78.4501, -76.9501)
  line L4 (65, -84.65) -> (65, -83.9)
  line L5 (55, -86.9) -> (65, -86.9)
  line L6 (55, -88.5) -> (55, -86.9)
  line L7 (65, -88.5) -> (55, -88.5)
  curve K6 (90, -63.5) -> (65, -88.5)
  line L8 (90, -53.5) -> (90, -63.5)
  line L9 (88.4, -53.5) -> (90, -53.5)
  line L10 (88.4, -63.5) -> (88.4, -53.5)
  line L11 (86.7843, -67.1) -> (88.3691, -67.1)
  line L12 (68.6, -86.8638) -> (68.6, -85.2845)
  line L13 (65, -86.9) -> (65, -86.15)
  line L14 (87.65, -63.5) -> (88.4, -63.5)
  arc A1 centre (86.9, -63.9) radius 0.85 clockwise from (87.65, -63.5) to (86.15, -63.5)
  arc A2 centre (65.4, -85.4) radius 0.85 clockwise from (65, -84.65) to (65, -86.15)
  point P22 (88.3691, -67.1)
  point P23 (86.7843, -67.1)
  point P24 (68.6, -85.2845)
  point P25 (68.6, -86.8638)
  coincident K1 P22
  coincident K3 P23
  horizontal L11
  coincident K2 P24
  coincident K1 P25
  vertical L12
  dimension "d625" distance L2 L11 = 2
  dimension "d626" distance L1 L12 = 2
extrude "Estrusione7" add sketch "Schizzo7" profile of K1 L1 K2 K3 L2 L11 L12 against normal blind 110
hole "Foratura2" HoleDepth 6 HoleDiameter 3.5 TipAngle 180 CSDiameter 6.7 CSAngle 90
mirror "Specchio1" mirrorStitchTolerance 0.1
work_plane "Piano di lavoro3" AlongDistance -8.6
work_plane "Piano di lavoro4" AlongDistance -8.6
sketch "Schizzo9" plane through (0, -81.4, 0) normal (0, -1, 0) x axis (-1, 0, 0)
  line L1 (-135, -14) -> (-135, 23.5)
  line L2 (-142.5, -14) -> (-160, -14)
  circle C1 centre (-143.321, -6.5) radius 1.75
  point P2 (-143.321, -6.5)
  dimension "d636" distance P2 L1 = 8.321
  dimension "d637" diameter C1 = 3.5
  dimension "d638" distance P2 L2 = 7.5
offset_faces "FacceDiOffset1" distance -0.2
offset_faces "FacceDiOffset2" distance -0.1
offset_faces "FacceDiOffset3" distance -0.1
sketch "Schizzo1" plane through (0, 0, -86.9) normal (0, 0, 1) x axis (-1, 0, 0)
  line L1 (-125, 0) -> (-135, 0)
  line L2 (-125, 25) -> (-125, 0)
  curve K1 (-95, 55) -> (-125, 25)
  line L3 (0, 55) -> (-95, 55)
  line L4 (0, 65) -> (0, 55)
  curve K2 (-95, 55) -> (-125, 25)
  line L5 (0, 55) -> (-95, 55)
  line L6 (-125, 0) -> (-125, 25)
  line L7 (0, 64.5) -> (-95, 64.5)
  curve K3 (-95, 64.5) -> (-134.5, 25)
  line L8 (-134.5, 0) -> (-134.5, 25)
  line L9 (0, 0) -> (0, 55)
  line L10 (-125, 0) -> (0, 0)
  line L11 (-95, 65) -> (0, 65)
  curve K4 (-135, 25) -> (-95, 65)
  line L12 (-135, 0) -> (-135, 25)
  circle C1 centre (-95, 60) radius 1.75
  circle C2 centre (-130, 25) radius 1.75
  circle C3 centre (-32, 60) radius 1.75
  circle C4 centre (-130, 25) radius 1.75
  circle C5 centre (-95, 60) radius 1.75
  circle C6 centre (-32, 60) radius 1.75
  point P9 (0, 55)
  point P22 (0, 55)
  point P14 (-125, 0)
  point P24 (-125, 0)
  coincident P9 P22
  coincident P14 P24
  horizontal L10
  vertical L9
  dimension "d620" = -9.5
extrude "Estrusione1" new body sketch "Schizzo1" profile of C1 C2 C3 L1 L2 K1 L3 L4 K2 L5 L6 L7 K3 L8 C4 C5 C6 L9 L10 along normal blind 3
work_plane "Piano di lavoro6" AlongDistance 3
sketch "Schizzo16" plane through (148.4, 0, 0) normal (-1, 0, 0) x axis (0, -1, 0)
  line L1 (82.5735, -43.5) -> (81.5735, -43.5)
  circle C1 centre (81.5735, -43.5) radius 3.5
  circle C2 centre (82.5735, -43.5) radius 5.5
  point P2 (81.5735, -43.5)
  point P4 (81.5735, -43.5)
  point P3 (82.5735, -43.5)
  point P5 (82.5735, -43.5)
  coincident P2 P4
  coincident P3 P5
  horizontal L1
  dimension "d678" diameter C2 = 11
  dimension "d713" distance P4 P5 = 1
extrude "Estrusione13" add sketch "Schizzo16" profile of C1 C2 against normal blind 6
sketch "Schizzo17" plane through (154.4, 0, 0) normal (1, 0, 0) x axis (0, 1, 0)
  line L1 (-87.2477, -40.6013) -> (-87.2477, -46.3987)
  arc A1 centre (-82.5735, -43.5) radius 5.5 clockwise from (-87.2477, -40.6013) to (-87.2477, -46.3987)
sketch "Schizzo18" plane through (0, 0, 14) normal (0, 0, 1) x axis (-1, 0, 0)
  line L1 (-135, 88.4) -> (-135, 87.65)
  line L2 (-125, 88.4) -> (-135, 88.4)
  line L3 (-125, 90) -> (-125, 88.4)
  line L4 (-160, 90) -> (-125, 90)
  line L5 (-160, 88.4) -> (-160, 90)
  curve K1 (-142.5, 81.4) -> (-160, 88.4)
  curve K2 (-135, 85.4) -> (-142.5, 81.4)
  line L6 (-135, 86.15) -> (-135, 85.4)
  line L7 (-139.6, 88.4) -> (-150.8209, 88.4)
  line L8 (-138.6, 87.4) -> (-139.6, 88.4)
  line L9 (-138.6, 87.0053) -> (-138.6, 87.4)
  line L10 (-138.6, 87.0053) -> (-139.3951, 85.3988)
  curve K3 (-142.5, 83) -> (-139.3951, 85.3988)
  curve K4 (-151.0572, 87.4594) -> (-142.5, 83)
  curve K5 (-150.8209, 88.4) -> (-151.0572, 87.4594)
  line L11 (-142.5, 72.162) -> (-142.5, 81.4)
  line L12 (-160, 72.162) -> (-142.5, 72.162)
  line L13 (-160, 88.4) -> (-160, 72.162)
  arc A1 centre (-135.4, 86.9) radius 0.85 clockwise from (-135, 86.15) to (-135, 87.65)
  point P10 (-142.5, 81.4)
  point P19 (-142.5, 81.4)
  point P9 (-160, 88.4)
  point P22 (-160, 88.4)
  coincident P10 P19
  vertical L11
  perpendicular L11 L12
  coincident P9 P22
  vertical L13
extrude "Estrusione14" cut sketch "Schizzo18" profile of K1 L11 L12 L13 against normal blind 72.864
sketch "Schizzo19" plane through (148.4, 0, 0) normal (-1, 0, 0) x axis (0, -1, 0)
  circle C1 centre (81.5735, -43.5) radius 2.45
  circle C2 centre (81.5735, -43.5) radius 5
  concentric C1 C2
  dimension "d683" diameter C2 = 10
extrude "Estrusione15" add sketch "Schizzo19" along normal blind 5.9
sketch "Schizzo20" plane through (148.4, 0, 0) normal (1, 0, 0) x axis (0, 1, 0)
  line L1 (-83.9651, -39.109) -> (-83.9651, -47.891)
  arc A1 centre (-81.5735, -43.5) radius 5 clockwise from (-83.9651, -39.109) to (-83.9651, -47.891)
  circle C1 centre (-81.5735, -43.5) radius 5
  concentric A1 C1
  dimension "d686" diameter C1 = 10
extrude "Estrusione16" cut sketch "Schizzo20" along normal blind 7.718
fillet "Raccordo1" radius 3
fillet "Raccordo2" radius 5
fillet "Raccordo3" radius 1
fillet "Raccordo4" StartRadius 3 EndRadius 3 MidRadius 0.2 MidParams 0.5
sketch "Schizzo21" plane through (148.4, 0, 0) normal (1, 0, 0) x axis (0, 1, 0)
  curve K1 (-83.9651, -49.4206) -> (-79.9057, -47.4498)
  curve K2 (-84.564, -39.4928) -> (-83.9651, -38.4409)
  curve K3 (-79.9057, -47.4498) -> (-79.9058, -39.5505)
  curve K4 (-79.9058, -39.5505) -> (-83.9651, -37.58)
  line L1 (-83.9651, -37.58) -> (-83.9651, -38.4409)
  curve K5 (-83.9651, -48.5591) -> (-84.564, -47.5072)
  line L2 (-83.9651, -48.5591) -> (-83.9651, -49.4206)
  arc A1 centre (-81.5735, -43.5) radius 5 clockwise from (-85.8748, -40.9507) to (-84.564, -39.4928)
  arc A2 centre (-81.5735, -43.5) radius 5 clockwise from (-85.8748, -46.0493) to (-85.8748, -40.9507)
  arc A3 centre (-81.5735, -43.5) radius 5 clockwise from (-84.564, -47.5072) to (-85.8748, -46.0493)
  circle C1 centre (-81.5735, -43.5) radius 0.75
  dimension "d697" diameter C1 = 1.5
extrude "Estrusione17" cut sketch "Schizzo21" profile of C1 against normal blind 5.8
component_insert "Inserimento componente1"
joint "Assembla1" alignAngle 180 alignOffsetX 0 alignOffsetY 0 alignOffsetZ 0
mirror "Specchio3" mirrorStitchTolerance 0.1
sketch "Schizzo1" plane through (0, 0, 80) normal (0, 0, -1) x axis (1, 0, 0)
  line L1 (131.5, 70.5) -> (131.5, -70.5)
  line L2 (-121.5, 80.5) -> (121.5, 80.5)
  line L3 (-131.5, -70.5) -> (-131.5, 70.5)
  line L4 (121.5, -80.5) -> (-121.5, -80.5)
  line L5 (130.8, -70.5) -> (130.8, 70.5)
  line L6 (-121.5, -79.8) -> (121.5, -79.8)
  line L7 (-130.8, 70.5) -> (-130.8, -70.5)
  line L8 (121.5, 79.8) -> (-121.5, 79.8)
  line L9 (85, 65) -> (85, 90)
  line L10 (160, 90) -> (85, 90)
  line L11 (160, 65) -> (160, 90)
  line L12 (85, 65) -> (160, 65)
  line L13 (28.65, 90) -> (35.35, 90)
  line L14 (126.65, 90) -> (133.35, 90)
  line L15 (91.65, 90) -> (98.35, 90)
  line L16 (98.35, 90) -> (91.65, 90)
  line L17 (133.35, 90) -> (126.65, 90)
  line L18 (35.35, 90) -> (28.65, 90)
  line L19 (160, 90) -> (85, 90)
  line L20 (85, 90) -> (160, 90)
  line L21 (0, 90) -> (85, 90)
  line L22 (95, 90) -> (0, 90)
  line L23 (125, 90) -> (95, 90)
  line L24 (125, 90) -> (95, 90)
  line L25 (0, 90) -> (95, 90)
  line L26 (85, 90) -> (0, 90)
  line L27 (135, 85.4) -> (129.7095, 85.4)
  line L28 (135, 85.4) -> (95, 85.4)
  line L29 (110, 85.4) -> (95, 85.4)
  line L30 (110.0047, 85.4) -> (110, 85.4)
  line L31 (129.7095, 85.4) -> (110.0047, 85.4)
  curve K1 (140.5791, 82.0476) -> (142.5, 81.4)
  curve K2 (142.5, 81.4) -> (135, 85.4)
  curve K3 (142.5, 81.4) -> (135, 85.4)
  curve K4 (140.5791, 82.0476) -> (142.5, 81.4)
  line L32 (135, 85.4) -> (135, 90)
  line L33 (135, 75.4) -> (135, 85.4)
  line L34 (141, 75.4) -> (141, 81.7819)
  line L35 (141, 75.4) -> (135, 75.4)
  arc A1 centre (121.5, -70.5) radius 10 clockwise from (131.5, -70.5) to (121.5, -80.5)
  arc A2 centre (121.5, 70.5) radius 10 clockwise from (121.5, 80.5) to (131.5, 70.5)
  arc A3 centre (-121.5, 70.5) radius 10 clockwise from (-131.5, 70.5) to (-121.5, 80.5)
  arc A4 centre (-121.5, -70.5) radius 10 clockwise from (-121.5, -80.5) to (-131.5, -70.5)
  arc A5 centre (121.5, 70.5) radius 9.3 clockwise from (121.5, 79.8) to (130.8, 70.5)
  arc A6 centre (121.5, -70.5) radius 9.3 clockwise from (130.8, -70.5) to (121.5, -79.8)
  arc A7 centre (-121.5, -70.5) radius 9.3 clockwise from (-121.5, -79.8) to (-130.8, -70.5)
  arc A8 centre (-121.5, 70.5) radius 9.3 clockwise from (-130.8, 70.5) to (-121.5, 79.8)
  point P45 (135, 90)
  point P46 (135, 85.4)
  point P48 (141, 81.7819)
  point P47 (135, 75.4)
  coincident L17 P45
  coincident L27 P46
  parallel L1 L33
  coincident K4 P48
  vertical L34
  perpendicular L34 L35
  dimension "d714" distance L11 L32 = 25
  dimension "d715" distance P46 P47 = 10
  dimension "d716" distance L33 L34 = 6
extrude "Estrusione1" new body sketch "Schizzo1" profile of K1 K2 K3 K4 L33 L34 L35 along normal blind 16
sketch "Schizzo2" plane through (0, 0, 80) normal (0, 0, 1) x axis (-1, 0, 0)
  line L1 (-135, 85.4) -> (-135, 75.4)
  curve K1 (-140.5791, 82.0476) -> (-135, 85.4)
  curve K2 (-140.5791, 82.0476) -> (-140.6931, 81.9682)
  line L2 (-140.6932, 81.9682) -> (-140.6931, 81.9682)
  curve K3 (-140.6932, 81.9682) -> (-140.9375, 81.8166)
  line L3 (-141, 75.4) -> (-141, 81.7819)
  line L4 (-135, 75.4) -> (-141, 75.4)
  line L5 (-126, 75.4) -> (-135, 75.4)
  line L6 (-126, 77.2) -> (-126, 75.4)
  curve K4 (-130, 77.2) -> (-126, 77.2)
  curve K5 (-132, 80.4) -> (-130, 77.2)
  curve K6 (-132, 85.4) -> (-132, 80.4)
  curve K7 (-135, 85.4) -> (-132, 85.4)
  curve K8 (-135, 85.4) -> (-126, 77.2)
  curve K9 (-141, 81.7819) -> (-140.5791, 82.0476)
  curve K10 (-142.3179, 80.3941) -> (-141, 81.7819)
  curve K11 (-143, 77.0196) -> (-142.3179, 80.3941)
  curve K12 (-143, 75.4) -> (-143, 77.0196)
  curve K13 (-143, 75.4) -> (-140.5791, 82.0476)
  line L7 (-141, 75.4) -> (-143, 75.4)
  closed curve K14 centre (-141.1774, 82.1553)
  point P2 (-135, 75.4)
  point P11 (-135, 75.4)
  point P8 (-141, 81.7819)
  point P17 (-141, 81.7819)
  point P10 (-141, 75.4)
  point P21 (-141, 75.4)
  point P13 (-126, 77.2)
  point P14 (-130, 77.2)
  point P15 (-132, 80.4)
  point P16 (-132, 85.4)
  point P3 (-135, 85.4)
  point P12 (-126, 75.4)
  point P20 (-143, 75.4)
  coincident P2 P11
  perpendicular L1 L5
  perpendicular L4 L6
  horizontal K7
  vertical K6
  horizontal K4
  coincident P8 P17
  coincident P10 P21
  horizontal L7
  vertical K12
  dimension "d719" distance P13 P14 = 4
  dimension "d720" distance P15 P16 = 5
  dimension "d721" distance P3 P16 = 3
  dimension "d722" distance P12 P13 = 1.8
  dimension "d742" distance P11 P12 = 9
  dimension "d757" distance P20 P21 = 2
extrude "Estrusione2" add sketch "Schizzo2" profile of L1 L3 L5 L6 K8 K13 L7 against normal blind 16
sketch "Schizzo6" plane through (0, 0, 80) normal (0, 0, 1) x axis (-1, 0, 0)
  curve K1 (-140.5791, 82.0476) -> (-135, 85.4)
  curve K2 (-140.5791, 82.0476) -> (-140.6931, 81.9682)
  line L1 (-140.6932, 81.9682) -> (-140.6931, 81.9682)
  curve K3 (-140.6932, 81.9682) -> (-140.9375, 81.8166)
  line L2 (-141, 81.6497) -> (-141, 81.7819)
  curve K4 (-143, 75.4) -> (-141, 81.6497)
  line L3 (-126, 75.4) -> (-143, 75.4)
  line L4 (-126, 77.2) -> (-126, 75.4)
  curve K5 (-135, 85.4) -> (-126, 77.2)
  line L5 (-140.5791, 82.0476) -> (-141, 81.6497)
  closed curve K6 centre (-141.1774, 82.1553)
  point P9 (-141, 81.6497)
  point P13 (-141, 81.6497)
  point P3 (-140.5791, 82.0476)
  point P14 (-140.5791, 82.0476)
  coincident P9 P13
  coincident P3 P14
extrude "Estrusione4" cut sketch "Schizzo6" profile of K2 L1 K3 K6 L2 L5 against normal blind 16
sketch "Schizzo3" plane through (0, -75.4, 0) normal (0, 1, 0) x axis (-1, 0, 0)
  line L1 (-143, 80) -> (-126, 80)
  line L2 (-126, 64) -> (-143, 64)
  line L3 (-126, 80) -> (-126, 64)
  line L4 (-139, 64) -> (-139, 80)
  line L5 (-143, 64) -> (-143, 80)
  point P6 (-139, 80)
  point P7 (-139, 64)
  point P8 (-139, 76)
  point P9 (-139, 68)
  coincident L1 P6
  coincident L2 P7
  perpendicular L2 L4
  coincident L4 P8
  coincident L4 P9
  dimension "d727" distance L2 P9 = 4
  dimension "d728" distance L1 P8 = 4
  dimension "d756" distance L4 L5 = 4
hole "Foratura1" HoleDepth 12 HoleDiameter 3.5 TipAngle 180
work_plane "Piano di lavoro1" AlongDistance -6
sketch "Schizzo7" plane through (0, -81.4, 0) normal (0, 1, 0) x axis (1, 0, 0)
  line L1 (140.75, -68) -> (140.75, -76)
  line L2 (137.25, -76) -> (137.25, -68)
  line L3 (141.25, -68) -> (141.25, -76)
  line L4 (136.75, -76) -> (136.75, -68)
  circle C1 centre (139, -76) radius 1.75
  circle C2 centre (139, -68) radius 1.75
  arc A1 centre (139, -68) radius 1.75 clockwise from (137.25, -68) to (140.75, -68)
  arc A2 centre (139, -76) radius 1.75 clockwise from (140.75, -76) to (137.25, -76)
  arc A3 centre (139, -68) radius 2.25 clockwise from (136.75, -68) to (141.25, -68)
  arc A4 centre (139, -76) radius 2.25 clockwise from (141.25, -76) to (136.75, -76)
  point P4 (140.75, -76)
  point P5 (140.75, -68)
  point P6 (137.25, -68)
  point P7 (137.25, -76)
  coincident C1 P4
  coincident C2 P5
  tangent C2 L1
  coincident C2 P6
  coincident C1 P7
  tangent C1 L2
  vertical L2
  tangent C1 L1
  concentric C1 A2
  concentric C2 A1
  dimension "d942" = 0.5
extrude "Estrusione5" cut sketch "Schizzo7" against normal blind 7.755
fillet "Raccordo1" radius 2 1
sketch "Schizzo4" plane through (0, -75.4, 0) normal (0, 1, 0) x axis (-1, 0, 0)
  curve K1 (-126, 78) -> (-128, 80)
  line L1 (-142, 80) -> (-128, 80)
  line L2 (-128, 64) -> (-142, 64)
  curve K2 (-128, 64) -> (-126, 66)
  line L3 (-126, 78) -> (-126, 66)
  line L4 (0, 104.9501) -> (0, 91.5)
  line L5 (0, 15.9207) -> (0, 91.5)
  line L6 (0, 80) -> (-128, 80)
  line L7 (0, 64) -> (-128, 64)
  line L8 (0, 64) -> (0, 80)
  line L9 (-143, 65) -> (-143, 79)
  curve K3 (-142, 80) -> (-143, 79)
  curve K4 (-143, 65) -> (-142, 64)
  circle C1 centre (-139, 76) radius 1.75
  circle C2 centre (-139, 68) radius 1.75
  point P8 (0, 91.5)
  point P10 (0, 91.5)
  point P2 (-128, 80)
  point P12 (-128, 80)
  point P13 (0, 80)
  point P6 (-128, 64)
  point P14 (-128, 64)
  point P15 (0, 64)
  coincident P8 P10
  parallel L4 L5
  coincident P2 P12
  coincident L5 P13
  coincident P6 P14
  coincident L5 P15
  horizontal L6
extrude "Estrusione3" new body sketch "Schizzo4" profile of K1 L1 L2 K2 L3 L6 L7 L8 C1 C2 L9 K3 K4 along normal blind 3 bodies "STAFFA"
sketch "Schizzo22" plane through (0, -90, 0) normal (0, -1, 0) x axis (1, 0, 0)
  line L1 (160, -63.5) -> (85, -63.5)
  line L2 (160, 91.5) -> (160, -63.5)
  line L3 (85, 91.5) -> (160, 91.5)
  line L4 (0, 91.5) -> (85, 91.5)
  line L5 (0, 81.5) -> (0, 91.5)
  line L6 (95, 81.5) -> (0, 81.5)
  curve K1 (125, 51.5) -> (95, 81.5)
  line L7 (125, -23.5) -> (125, 51.5)
  curve K2 (125, -23.5) -> (95, -53.5)
  line L8 (0, -53.5) -> (95, -53.5)
  line L9 (0, -63.5) -> (0, -53.5)
  line L10 (85, -63.5) -> (0, -63.5)
  line L11 (142, 80) -> (0, 80)
  line L12 (0, 64) -> (142, 64)
  line L13 (0, 80) -> (0, 64)
  curve K3 (140.5791, 76.7542) -> (140.5791, 75.2458)
  curve K4 (143, 79) -> (142, 80)
  line L14 (143, 65) -> (143, 79)
  curve K5 (142, 64) -> (143, 65)
  circle C1 centre (32, 86.5) radius 3.35
  circle C2 centre (130, 51.5) radius 3.35
  circle C3 centre (95, 86.5) radius 3.35
  circle C4 centre (95, -58.5) radius 3.35
  circle C5 centre (130, -23.5) radius 3.35
  circle C6 centre (32, -58.5) radius 3.35
  circle C7 centre (139, 76) radius 1.5
  circle C8 centre (139, 68) radius 1.5
  arc A1 centre (139, 76) radius 1.75 clockwise from (140.5791, 76.7542) to (140.5791, 75.2458)
  circle C9 centre (139, 76) radius 1.75
  circle C10 centre (139, 68) radius 1.75
  circle C11 centre (139, 76) radius 1.75
  circle C12 centre (139, 68) radius 1.75
  concentric C7 A1
  concentric C8 C10
  dimension "d743" diameter C7 = 3
  dimension "d744" diameter C8 = 3
offset_faces "FacceDiOffset2" distance 1
extrude "Estrusione18" cut sketch "Schizzo22" profile of C7 C8 blind -7.192 from offset -0.8
component_from_bodies "Corpo->Comp1"
component_from_bodies "Corpo->Comp2"
copy_paste "CopiaIncolla1"
copy_paste "CopiaIncolla2"
sketch "Schizzo23" plane through (0, -90, 0) normal (0, -1, 0) x axis (1, 0, 0)
  line L1 (160, -63.5) -> (85, -63.5)
  line L2 (160, 91.5) -> (160, -63.5)
  line L3 (85, 91.5) -> (160, 91.5)
  line L4 (0, 91.5) -> (85, 91.5)
  line L5 (0, 81.5) -> (0, 91.5)
  line L6 (95, 81.5) -> (0, 81.5)
  curve K1 (125, 51.5) -> (95, 81.5)
  line L7 (125, -23.5) -> (125, 51.5)
  curve K2 (125, -23.5) -> (95, -53.5)
  line L8 (0, -53.5) -> (95, -53.5)
  line L9 (0, -63.5) -> (0, -53.5)
  line L10 (85, -63.5) -> (0, -63.5)
  circle C1 centre (32, 86.5) radius 3.35
  circle C2 centre (130, 51.5) radius 3.35
  circle C3 centre (95, 86.5) radius 3.35
  circle C4 centre (95, -58.5) radius 3.35
  circle C5 centre (130, -23.5) radius 3.35
  circle C6 centre (32, -58.5) radius 3.35
  circle C7 centre (139, -4) radius 1.5
  circle C8 centre (139, -12) radius 1.5
  circle C9 centre (139, -12) radius 1.75
  circle C10 centre (139, -4) radius 1.75
  circle C11 centre (139, -12) radius 1.75
  point P21 (139, -12)
  point P22 (139, -12)
  concentric C7 C10
  coincident P21 P22
  dimension "d749" diameter C7 = 3
  dimension "d750" diameter C8 = 3
extrude "Estrusione19" cut sketch "Schizzo23" profile of C7 C8 against normal blind 9.545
